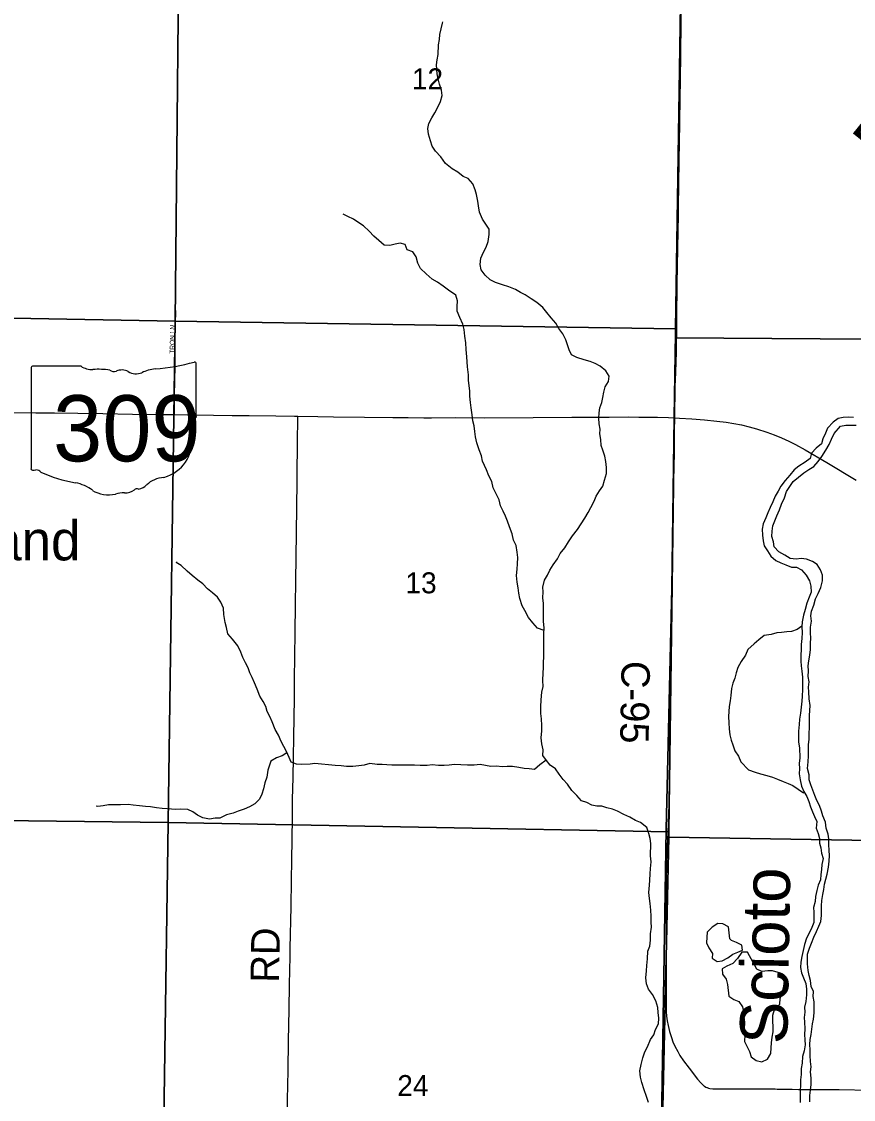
# Model space of a CAD drawing. Extents: x 1584893 to 1934202, y 663575 to 1091909.
# Drawn here: x 1770359 to 1779115, y 945119 to 956462 of the extents above; entities that cross this region are included whole.
import ezdxf

# ---------------------------------------------------------------- set-up
doc = ezdxf.new("R2010")
doc.units = 0
for name, color, linetype in [('GM_X_County_Road', 7, 'Continuous'), ('GM_X_County_Road_Text', 7, 'Continuous'), ('GM_X_Major_River', 7, 'Continuous'), ('GM_X_Major_River_Text', 7, 'Continuous'), ('GM_X_Minor_Lake', 7, 'Continuous'), ('GM_X_Minor_River', 7, 'Continuous'), ('GM_X_Section', 7, 'Continuous'), ('GM_X_Section_Text', 7, 'Continuous'), ('GM_X_State_Location', 7, 'Continuous'), ('GM_X_State_Route', 7, 'Continuous'), ('GM_X_State_Shield', 7, 'Continuous'), ('GM_X_Township', 7, 'Continuous'), ('GM_X_Township_Road', 7, 'Continuous'), ('GM_X_Township_Road_Text', 7, 'Continuous'), ('GM_X_Township_Subdivision', 7, 'Continuous'), ('GM_X_Township_Subdivision_Text', 7, 'Continuous'), ('GM_X_Unincorporated_Text', 7, 'Continuous')]:
    doc.layers.add(name, color=color, linetype=linetype)

msp = doc.modelspace()

# ---------------------------------------------------------------- linework, layer by layer
at = {"layer": 'GM_X_County_Road'}
for points in [[(1777306, 956950), (1777299, 956441), (1777295, 956129), (1777291, 955834), (1777288, 955670), (1777283, 955391), (1777276, 954998), (1777272, 954752), (1777269, 954506), (1777269, 954423), (1777265, 954259), (1777256, 953702), (1777251, 953341), (1777251, 953177), (1777249, 953078), (1777247, 952980), (1777244, 952882), (1777240, 952768), (1777236, 952621), (1777233, 952490), (1777231, 952424), (1777231, 952326), (1777230, 952292)], [(1777230, 952292), (1777229, 952227), (1777228, 951915), (1777222, 951653), (1777216, 951292), (1777214, 951079), (1777208, 950767), (1777205, 950570), (1777199, 950160), (1777190, 949602), (1777183, 949192), (1777180, 948848), (1777178, 948667), (1777176, 948503), (1777170, 948224), (1777160, 947929), (1777151, 947716), (1777146, 947585), (1777143, 947421), (1777143, 947241), (1777145, 946945), (1777145, 946749), (1777145, 946601), (1777144, 946289), (1777143, 946125), (1777145, 946058)], [(1777145, 946058), (1777145, 946043), (1777148, 945995), (1777155, 945946), (1777164, 945898), (1777180, 945835), (1777198, 945772), (1777215, 945726), (1777235, 945681), (1777265, 945623), (1777289, 945581), (1777325, 945526), (1777384, 945447), (1777475, 945332), (1777507, 945294), (1777530, 945272), (1777539, 945263), (1777547, 945257), (1777561, 945249), (1777570, 945245)], [(1777570, 945245), (1777575, 945243), (1777588, 945238), (1777604, 945234), (1777636, 945231), (1777685, 945229), (1777980, 945232), (1778291, 945229), (1778313, 945228)], [(1778313, 945228), (1778471, 945226)], [(1778471, 945226), (1778537, 945225), (1778964, 945222), (1779292, 945218), (1779817, 945212), (1780358, 945206), (1780521, 945203), (1780653, 945201), (1781014, 945196), (1781326, 945193), (1781637, 945190), (1782129, 945184), (1782490, 945179), (1782701, 945178)]]:
    msp.add_lwpolyline(points, dxfattribs=at)
at = {"layer": 'GM_X_Major_River'}
for points in [[(1779117, 952297), (1779065, 952300), (1779007, 952295), (1778953, 952284), (1778902, 952245), (1778843, 952184), (1778820, 952132), (1778794, 952072), (1778777, 952019), (1778724, 951974), (1778673, 951920), (1778660, 951865), (1778606, 951827)], [(1778388, 951449), (1778409, 951515), (1778444, 951570), (1778481, 951621), (1778535, 951668), (1778594, 951714), (1778646, 951747), (1778697, 951780), (1778744, 951833), (1778782, 951886), (1778823, 951950), (1778858, 952011), (1778885, 952067), (1778912, 952126), (1778979, 952203), (1779035, 952216), (1779143, 952215)], [(1778606, 951827), (1778541, 951784), (1778491, 951743), (1778446, 951690), (1778397, 951633), (1778350, 951574), (1778321, 951520), (1778290, 951467), (1778266, 951407), (1778239, 951347), (1778212, 951292), (1778193, 951238), (1778166, 951176), (1778153, 951119), (1778156, 951057), (1778165, 950996), (1778176, 950944), (1778211, 950891), (1778246, 950837), (1778297, 950790), (1778349, 950765), (1778402, 950744), (1778462, 950719), (1778516, 950720), (1778567, 950691), (1778616, 950636), (1778651, 950576), (1778666, 950521), (1778669, 950459), (1778648, 950406), (1778623, 950340), (1778606, 950276), (1778589, 950214), (1778576, 950145), (1778571, 950091), (1778576, 950034), (1778571, 949971), (1778566, 949905), (1778565, 949853), (1778562, 949793), (1778561, 949732), (1778566, 949682), (1778571, 949626), (1778580, 949564), (1778577, 949498), (1778578, 949432), (1778575, 949364), (1778570, 949310), (1778563, 949246), (1778556, 949184), (1778547, 949122), (1778544, 949064), (1778537, 948996), (1778536, 948940), (1778537, 948880), (1778546, 948818), (1778552, 948714), (1778545, 948654), (1778546, 948600), (1778543, 948544), (1778554, 948482), (1778569, 948417), (1778594, 948359), (1778625, 948308), (1778644, 948256), (1778663, 948198), (1778685, 948145), (1778706, 948095), (1778731, 948044), (1778722, 947974), (1778745, 947918), (1778756, 947866), (1778759, 947816), (1778772, 947765), (1778777, 947711), (1778796, 947655), (1778783, 947591), (1778778, 947539), (1778771, 947485), (1778769, 947429), (1778744, 947373), (1778729, 947316), (1778716, 947256), (1778711, 947202), (1778696, 947140), (1778699, 947090), (1778697, 946982), (1778676, 946928), (1778649, 946869), (1778621, 946817), (1778600, 946749), (1778585, 946686), (1778570, 946622), (1778561, 946562), (1778558, 946506), (1778567, 946450), (1778590, 946397), (1778615, 946339), (1778620, 946281), (1778621, 946219), (1778612, 946149)], [(1778684, 945913), (1778694, 945965), (1778701, 946029), (1778702, 946087), (1778701, 946145), (1778692, 946203), (1778693, 946255), (1778670, 946308), (1778661, 946372), (1778648, 946424), (1778639, 946477), (1778632, 946547), (1778631, 946597), (1778632, 946647), (1778651, 946711), (1778672, 946762), (1778699, 946828), (1778726, 946887), (1778752, 946941), (1778773, 946993), (1778780, 947053), (1778779, 947107), (1778778, 947157), (1778781, 947213), (1778792, 947277), (1778803, 947328), (1778810, 947384), (1778823, 947438), (1778837, 947490), (1778853, 947564), (1778858, 947626), (1778861, 947686), (1778859, 947738), (1778855, 947802), (1778854, 947860), (1778850, 947910), (1778827, 947975), (1778819, 948037), (1778792, 948103), (1778779, 948154), (1778758, 948212), (1778730, 948264), (1778707, 948319), (1778686, 948375), (1778665, 948430), (1778650, 948482), (1778647, 948536), (1778632, 948602), (1778639, 948672), (1778642, 948736), (1778641, 948796), (1778640, 948850), (1778647, 948910), (1778648, 948972), (1778651, 949028), (1778652, 949094), (1778651, 949158), (1778654, 949212), (1778659, 949266), (1778650, 949333), (1778646, 949407), (1778642, 949457), (1778647, 949515), (1778638, 949571), (1778641, 949631), (1778638, 949681), (1778645, 949735), (1778654, 949795), (1778661, 949855), (1778664, 949921), (1778665, 949973), (1778664, 950031), (1778661, 950089), (1778672, 950153), (1778667, 950207), (1778672, 950259), (1778697, 950319), (1778716, 950388), (1778745, 950444), (1778772, 950506), (1778789, 950577), (1778790, 950637), (1778769, 950694), (1778734, 950750), (1778682, 950781), (1778621, 950804), (1778565, 950811), (1778511, 950806), (1778449, 950813), (1778392, 950846), (1778329, 950881), (1778280, 950936), (1778273, 950986), (1778257, 951043), (1778258, 951099), (1778265, 951155), (1778286, 951208), (1778309, 951262), (1778336, 951324), (1778359, 951385), (1778388, 951449)], [(1778612, 946149), (1778601, 946089), (1778602, 946037), (1778597, 945981), (1778600, 945931), (1778603, 945863), (1778598, 945803), (1778603, 945747), (1778606, 945692), (1778597, 945631), (1778580, 945571), (1778575, 945501), (1778564, 945445), (1778565, 945381), (1778556, 945325), (1778557, 945271), (1778554, 945209), (1778553, 945143), (1778554, 945087)], [(1778656, 945093), (1778657, 945161), (1778664, 945217), (1778671, 945277), (1778668, 945343), (1778661, 945409), (1778668, 945461), (1778661, 945517), (1778658, 945581), (1778659, 945640), (1778656, 945696), (1778659, 945748), (1778670, 945801), (1778684, 945913)]]:
    msp.add_lwpolyline(points, dxfattribs=at)
at = {"layer": 'GM_X_Minor_Lake'}
for points in [[(1777798, 946937), (1777741, 946966), (1777687, 946969), (1777626, 946932), (1777576, 946879), (1777573, 946825), (1777568, 946767), (1777593, 946715), (1777632, 946656), (1777629, 946604), (1777680, 946571), (1777732, 946578), (1777791, 946609), (1777845, 946646), (1777898, 946667), (1777948, 946691), (1777939, 946741), (1777883, 946770), (1777832, 946791), (1777814, 946809)], [(1777814, 946809), (1777798, 946937)], [(1778001, 946668), (1777940, 946669), (1777896, 946603), (1777846, 946550), (1777783, 946521), (1777733, 946492), (1777736, 946438), (1777775, 946385), (1777788, 946327), (1777802, 946207), (1777855, 946172), (1777909, 946149), (1777948, 946094), (1777959, 946042), (1777962, 945986), (1777967, 945932), (1777966, 945858), (1777971, 945799), (1777968, 945729), (1777993, 945679), (1778022, 945624), (1778039, 945568), (1778090, 945529), (1778152, 945514), (1778210, 945541), (1778245, 945601), (1778250, 945663), (1778251, 945715), (1778258, 945774), (1778269, 945830), (1778270, 945884), (1778265, 945941), (1778266, 946007), (1778285, 946066), (1778340, 946121), (1778345, 946181), (1778368, 946253), (1778383, 946307), (1778390, 946367), (1778375, 946425), (1778321, 946454), (1778264, 946471), (1778212, 946472), (1778150, 946465), (1778098, 946490)], [(1778098, 946490), (1778001, 946668)]]:
    msp.add_lwpolyline(points, dxfattribs=at)
at = {"layer": 'GM_X_Minor_River'}
for points in [[(1775134, 954693), (1775107, 954756), (1775060, 954809), (1775007, 954830), (1774951, 954879), (1774890, 954912), (1774821, 954969), (1774772, 955038), (1774716, 955097), (1774682, 955151), (1774663, 955208), (1774643, 955278), (1774636, 955336), (1774646, 955388), (1774677, 955450), (1774708, 955501), (1774745, 955569), (1774768, 955620), (1774785, 955684), (1774778, 955742), (1774759, 955805), (1774742, 955861), (1774733, 955911), (1774727, 956007), (1774733, 956059), (1774744, 956115), (1774746, 956219), (1774759, 956275), (1774762, 956327), (1774775, 956387), (1774788, 956445), (1774794, 956459)], [(1775830, 949125), (1775823, 949179), (1775824, 949251), (1775828, 949325), (1775835, 949405), (1775848, 949465), (1775845, 949529), (1775848, 949609), (1775851, 949661), (1775852, 949717), (1775857, 949775), (1775856, 949825), (1775855, 949889), (1775856, 949963), (1775855, 950019), (1775860, 950081), (1775851, 950149), (1775852, 950225), (1775851, 950275), (1775852, 950339), (1775847, 950396), (1775848, 950460), (1775845, 950510), (1775862, 950584), (1775893, 950637), (1775920, 950689), (1775955, 950746), (1776000, 950807), (1776029, 950865), (1776078, 950924), (1776117, 950987), (1776158, 951051), (1776211, 951118), (1776250, 951175), (1776286, 951235), (1776321, 951294), (1776350, 951348), (1776385, 951415), (1776408, 951467), (1776443, 951522), (1776476, 951574), (1776493, 951636), (1776514, 951707), (1776517, 951769), (1776508, 951831), (1776497, 951890), (1776476, 951952), (1776461, 952002), (1776456, 952064), (1776447, 952123), (1776448, 952173), (1776437, 952229), (1776436, 952287), (1776439, 952343), (1776447, 952397), (1776468, 952455), (1776477, 952506), (1776488, 952562), (1776503, 952618), (1776538, 952674), (1776543, 952730), (1776508, 952786), (1776449, 952837), (1776395, 952864), (1776342, 952885), (1776280, 952902), (1776203, 952928), (1776147, 952954), (1776124, 953007), (1776105, 953059), (1776088, 953114), (1776057, 953176), (1776014, 953233), (1775981, 953288), (1775934, 953344), (1775889, 953401), (1775846, 953454), (1775783, 953505), (1775722, 953544), (1775661, 953587), (1775609, 953610), (1775558, 953641), (1775488, 953670), (1775421, 953692), (1775347, 953715), (1775292, 953746), (1775237, 953793), (1775198, 953848), (1775185, 953904), (1775194, 953974), (1775221, 954035), (1775250, 954087), (1775271, 954148), (1775282, 954222), (1775281, 954276), (1775211, 954382), (1775180, 954458), (1775169, 954523), (1775160, 954573), (1775147, 954641), (1775134, 954693)], [(1775858, 950055), (1775790, 950080), (1775741, 950133), (1775694, 950190), (1775655, 950263), (1775628, 950315), (1775604, 950392), (1775593, 950448), (1775584, 950504), (1775575, 950564), (1775568, 950633), (1775575, 950699), (1775580, 950754), (1775581, 950823), (1775576, 950879), (1775565, 950947), (1775538, 951005), (1775521, 951070), (1775494, 951144), (1775473, 951205), (1775454, 951257), (1775429, 951308), (1775398, 951366), (1775387, 951428), (1775354, 951493), (1775324, 951556), (1775309, 951622), (1775276, 951680), (1775253, 951743), (1775212, 951836), (1775199, 951892), (1775174, 951954), (1775152, 952029), (1775137, 952091), (1775130, 952149), (1775121, 952208), (1775110, 952260), (1775103, 952324), (1775090, 952398), (1775085, 952452), (1775078, 952521), (1775077, 952577), (1775070, 952629), (1775063, 952689), (1775062, 952745), (1775051, 952829), (1775048, 952883), (1775047, 952935), (1775040, 953012), (1775035, 953082), (1775025, 953152), (1775016, 953222), (1775003, 953278), (1774970, 953349), (1774943, 953414), (1774944, 953464), (1774947, 953522), (1774930, 953582), (1774851, 953637), (1774798, 953676), (1774735, 953719), (1774679, 953750), (1774618, 953807), (1774559, 953864), (1774528, 953921), (1774511, 953987), (1774478, 954040), (1774419, 954059), (1774398, 954115), (1774342, 954130), (1774292, 954119), (1774236, 954106), (1774174, 954109), (1774119, 954158), (1774068, 954205), (1774017, 954256), (1773958, 954313), (1773907, 954344), (1773853, 954383), (1773794, 954410), (1773742, 954435), (1773744, 954433)], [(1775881, 948691), (1775814, 948639), (1775756, 948592), (1775700, 948597), (1775648, 948602), (1775592, 948613), (1775526, 948622), (1775469, 948623), (1775417, 948620), (1775357, 948625), (1775297, 948624), (1775243, 948633), (1775185, 948642), (1775121, 948635), (1775052, 948638), (1774982, 948641), (1774916, 948644), (1774860, 948637), (1774808, 948634), (1774746, 948633), (1774680, 948640), (1774628, 948633), (1774553, 948634), (1774495, 948637), (1774429, 948635), (1774319, 948636), (1774257, 948636), (1774205, 948640), (1774153, 948643), (1774100, 948644), (1774026, 948654), (1773966, 948635), (1773908, 948628), (1773846, 948623), (1773778, 948622), (1773724, 948629), (1773660, 948632), (1773590, 948641), (1773517, 948646), (1773445, 948654), (1773395, 948646), (1773305, 948642), (1773251, 948647), (1773198, 948668), (1773175, 948718), (1773146, 948779), (1773119, 948833), (1773092, 948886), (1773063, 948952), (1773028, 949013), (1772997, 949094), (1772972, 949150), (1772943, 949201), (1772928, 949255), (1772903, 949305), (1772868, 949362), (1772839, 949435), (1772810, 949503), (1772787, 949558), (1772762, 949610), (1772743, 949662), (1772716, 949715), (1772689, 949769), (1772668, 949826), (1772635, 949892), (1772580, 949963), (1772529, 950018), (1772517, 950087), (1772503, 950139), (1772487, 950223), (1772484, 950289), (1772455, 950352), (1772422, 950405), (1772367, 950450), (1772316, 950494), (1772267, 950545), (1772215, 950584), (1772154, 950631), (1772101, 950678), (1772038, 950739), (1771987, 950770), (1771995, 950776)], [(1778572, 950101), (1778521, 950065), (1778464, 950042), (1778413, 950039), (1778359, 950034), (1778307, 950031), (1778248, 950012), (1778176, 950001), (1778120, 949954), (1778069, 949915), (1778004, 949854), (1777977, 949795), (1777932, 949727), (1777899, 949666), (1777882, 949610), (1777867, 949552), (1777845, 949501), (1777832, 949445), (1777825, 949369), (1777816, 949313), (1777805, 949253), (1777804, 949203), (1777799, 949149), (1777804, 949083), (1777805, 949019), (1777814, 948955), (1777829, 948900), (1777844, 948850), (1777867, 948788), (1777904, 948731), (1777931, 948672), (1778011, 948589), (1778079, 948562), (1778136, 948547), (1778202, 948528), (1778261, 948509), (1778315, 948490), (1778374, 948465), (1778426, 948442), (1778478, 948421), (1778533, 948384), (1778590, 948347), (1778588, 948343)], [(1776957, 945086), (1776938, 945151), (1776913, 945219), (1776889, 945296), (1776872, 945354), (1776867, 945420), (1776880, 945488), (1776897, 945556), (1776918, 945619), (1776947, 945671), (1776980, 945748), (1777015, 945800), (1777030, 945854), (1777063, 945915), (1777068, 945975), (1777061, 946033), (1777056, 946085), (1777033, 946156), (1776998, 946223), (1776959, 946279), (1776936, 946336), (1776931, 946400), (1776938, 946472), (1776941, 946530), (1776948, 946600), (1776952, 946678), (1776970, 946733), (1776977, 946795), (1776979, 946861), (1776990, 946931), (1776987, 946983), (1776984, 947047), (1776983, 947111), (1776974, 947182), (1776969, 947232), (1776962, 947296), (1776969, 947374), (1776972, 947428), (1776975, 947494), (1776980, 947550), (1776985, 947620), (1776980, 947682), (1776982, 947814), (1776975, 947864), (1776962, 947918), (1776939, 947979), (1776872, 948032), (1776821, 948053), (1776761, 948090), (1776698, 948119), (1776631, 948152), (1776577, 948175), (1776519, 948188), (1776468, 948205), (1776414, 948206), (1776362, 948217), (1776309, 948242), (1776253, 948263), (1776204, 948318), (1776151, 948371), (1776104, 948436), (1776061, 948486), (1776016, 948543), (1775977, 948598), (1775922, 948635), (1775885, 948686), (1775846, 948738), (1775849, 948798), (1775836, 948861), (1775829, 948923), (1775834, 948999), (1775835, 949053), (1775830, 949125)], [(1773152, 948765), (1773101, 948736), (1773043, 948715), (1772984, 948680), (1772951, 948584), (1772942, 948512), (1772919, 948452), (1772906, 948387), (1772887, 948333), (1772862, 948279), (1772815, 948228), (1772759, 948199), (1772702, 948174), (1772638, 948151), (1772586, 948132), (1772516, 948115), (1772447, 948078), (1772395, 948079), (1772337, 948068), (1772268, 948083), (1772212, 948110), (1772161, 948145), (1772108, 948170), (1772034, 948174), (1771982, 948170), (1771892, 948176), (1771838, 948181), (1771780, 948186), (1771717, 948197), (1771663, 948200), (1771599, 948209), (1771535, 948216), (1771480, 948221), (1771400, 948218), (1771336, 948220), (1771274, 948219), (1771218, 948210), (1771160, 948203), (1771144, 948205)]]:
    msp.add_lwpolyline(points, dxfattribs=at)
at = {"layer": 'GM_X_Section'}
for points in [[(1766755, 958678), (1772029, 958632), (1771974, 953310), (1766658, 953408)], [(1772029, 958632), (1777320, 958548), (1777321, 958468), (1777240, 953230), (1771974, 953310)], [(1777321, 958468), (1782893, 958359), (1782828, 953094), (1777243, 953134), (1777240, 953230)], [(1766658, 953408), (1771974, 953310), (1771900, 948032), (1766608, 948095)], [(1771974, 953310), (1777240, 953230), (1777243, 953134), (1777170, 947934), (1771900, 948032)], [(1777243, 953134), (1782828, 953094), (1782734, 947786), (1777170, 947880), (1777170, 947934)], [(1766608, 948095), (1771900, 948032), (1771824, 942715), (1766481, 942794)], [(1771900, 948032), (1777170, 947934), (1777170, 947880), (1777056, 942654), (1771824, 942715)], [(1777170, 947880), (1782734, 947786), (1782632, 942486), (1777053, 942532), (1777056, 942654)]]:
    msp.add_lwpolyline(points, close=True, dxfattribs=at)
at = {"layer": 'GM_X_State_Route'}
for points in [[(1770279, 952347), (1770509, 952344), (1770706, 952343), (1770952, 952340), (1771214, 952336), (1771526, 952332), (1771821, 952328), (1771968, 952326), (1772379, 952321), (1772576, 952318), (1772756, 952315), (1773035, 952312), (1773232, 952310), (1773266, 952309), (1773478, 952305), (1773642, 952302), (1773970, 952300), (1774265, 952296), (1774429, 952294), (1774593, 952293)], [(1774593, 952293), (1774675, 952293), (1774921, 952294), (1775233, 952293), (1775742, 952295), (1776152, 952298), (1776332, 952300), (1776545, 952300), (1776742, 952301), (1776855, 952300)], [(1776855, 952300), (1777054, 952298), (1777169, 952296), (1777230, 952292), (1777284, 952290), (1777415, 952282), (1777546, 952270), (1777676, 952258), (1777774, 952246), (1777855, 952233), (1777936, 952217), (1778016, 952197), (1778095, 952175), (1778204, 952140), (1778282, 952112), (1778358, 952081), (1778433, 952047), (1778506, 952010), (1778607, 951954), (1778833, 951822), (1779144, 951637)]]:
    msp.add_lwpolyline(points, dxfattribs=at)
at = {"layer": 'GM_X_State_Shield'}
for p, q in [((1770458, 952816), (1770458, 951760)), ((1770985, 952834), (1770475, 952834)), ((1772198, 952308), (1772198, 952861)), ((1772198, 952308), (1772198, 952308))]:
    msp.add_line(p, q, dxfattribs=at)
for centre, major_axis, start_param, end_param in [((1771579, 954275), (1845, 0), 4.814394, 5.042369), ((1772179, 952863), (19.4, 0), 6.141152, 7.989035), ((1770478, 952819), (20.2, 0), 1.712693, 3.28349), ((1771106, 952957), (196, 0), 4.042523, 4.731795), ((1771171, 952241), (702, 0), 1.404758, 1.657858), ((1771331, 952824), (56.4, 0), 3.836095, 5.185415), ((1771413, 952702), (117, 0), 0.950623, 2.079405), ((1771565, 952869), (141, 0), 4.081561, 5.145723), ((1771814, 952512), (371, 0), 1.699011, 2.107814), ((1772178, 952306), (20.7, 0), 5.05454, 6.418171), ((1772194, 952267), (30, 0), 1.883978, 3.671073), ((1772003, 952197), (180, 0), 5.934695, 6.695948), ((1772268, 952077), (131, 0), 2.387724, 3.262537), ((1771682, 952006), (462, 0), 5.101752, 6.440018), ((1770478, 951757), (20.3, 0), 3.00124, 4.508301), ((1770481, 951865), (155, 0), 4.665946, 4.897461), ((1770513, 951699), (56, 0), 0.519207, 1.627899), ((1771220, 952648), (1333, 0), 4.195997, 4.488961), ((1771877, 951463), (253, 0), 1.647645, 2.488434), ((1770822, 951285), (417, 0), 0.823519, 1.323587), ((1771273, 951693), (265, 0), 4.026481, 4.996735), ((1771426, 951328), (217, 0), 1.495662, 1.94098), ((1771446, 951614), (141, 0), 4.691044, 5.507374), ((1771573, 951512), (39.7, 0), 1.147584, 2.315152), ((1771556, 951657), (149, 0), 4.937069, 5.64225)]:
    msp.add_ellipse(centre, major_axis=major_axis, ratio=0.8, start_param=start_param, end_param=end_param, dxfattribs=at)
at = {"layer": 'GM_X_Township'}
for points in [[(1779121, 932012), (1776888, 932016), (1777001, 937372), (1777059, 942660), (1777144, 947963), (1777203, 950501), (1777226, 952294), (1777326, 958526)], [(1777326, 958526), (1777226, 952294), (1777203, 950501), (1777144, 947963), (1777059, 942660), (1777001, 937372)]]:
    msp.add_lwpolyline(points, dxfattribs=at)
at = {"layer": 'GM_X_Township_Road'}
for points in [[(1773187, 946712), (1773195, 947146), (1773201, 947425), (1773203, 947638), (1773209, 948081), (1773212, 948277), (1773216, 948507), (1773220, 948720), (1773223, 948933), (1773230, 949343), (1773233, 949539), (1773239, 950031), (1773241, 950326), (1773244, 950572), (1773253, 951080), (1773259, 951621), (1773264, 952097), (1773266, 952228), (1773266, 952277), (1773266, 952309)], [(1773112, 942720), (1773113, 942754), (1773120, 942983), (1773124, 943278), (1773129, 943491), (1773143, 944262), (1773152, 944803), (1773158, 945114), (1773164, 945425), (1773169, 945737), (1773175, 946065), (1773180, 946327), (1773185, 946622), (1773187, 946712)]]:
    msp.add_lwpolyline(points, dxfattribs=at)
at = {"layer": 'GM_X_Township_Subdivision'}
msp.add_lwpolyline([(1771968, 952326), (1771968, 952345), (1771968, 952412), (1771970, 952526), (1771974, 952836), (1771977, 953178), (1771979, 953275), (1771981, 953421)], dxfattribs=at)

# ---------------------------------------------------------------- texts
at = {"layer": 'GM_X_County_Road_Text'}
msp.add_text('C-95', height=300, rotation=268.9749, dxfattribs=at).set_placement((1776674, 949736))
at = {"layer": 'GM_X_Major_River_Text'}
for s, rotation, p in [('River', 51.0154, (1779463, 954928)), ('Scioto', 89.0148, (1778418, 945698))]:
    msp.add_text(s, height=500.1, rotation=rotation, dxfattribs=at).set_placement(p)
at = {"layer": 'GM_X_Section_Text'}
for s, p in [('12', (1774467, 955749)), ('13', (1774399, 950445)), ('24', (1774313, 945154))]:
    msp.add_text(s, height=221, rotation=0, dxfattribs=at).set_placement(p)
at = {"layer": 'GM_X_State_Location'}
for s in ['s', 'r']:
    msp.add_text(s, height=1, dxfattribs=at).set_placement((1771309, 952218))
msp.add_text('309', height=1, rotation=0, dxfattribs=at).set_placement((1770956, 952145))
at = {"layer": 'GM_X_State_Shield'}
msp.add_text('309', height=696.1, dxfattribs=at).set_placement((1770690, 951834))
at = {"layer": 'GM_X_Township_Road_Text'}
msp.add_text('RD', height=300, rotation=89.0203, dxfattribs=at).set_placement((1773068, 946346))
at = {"layer": 'GM_X_Township_Subdivision_Text'}
msp.add_text('TRON LN', height=50, rotation=89.0457, dxfattribs=at).set_placement((1771967, 952966))
at = {"layer": 'GM_X_Unincorporated_Text'}
msp.add_text('Island', height=417, rotation=0, dxfattribs=at).set_placement((1769491, 950792))

doc.saveas('drawing.dxf')
